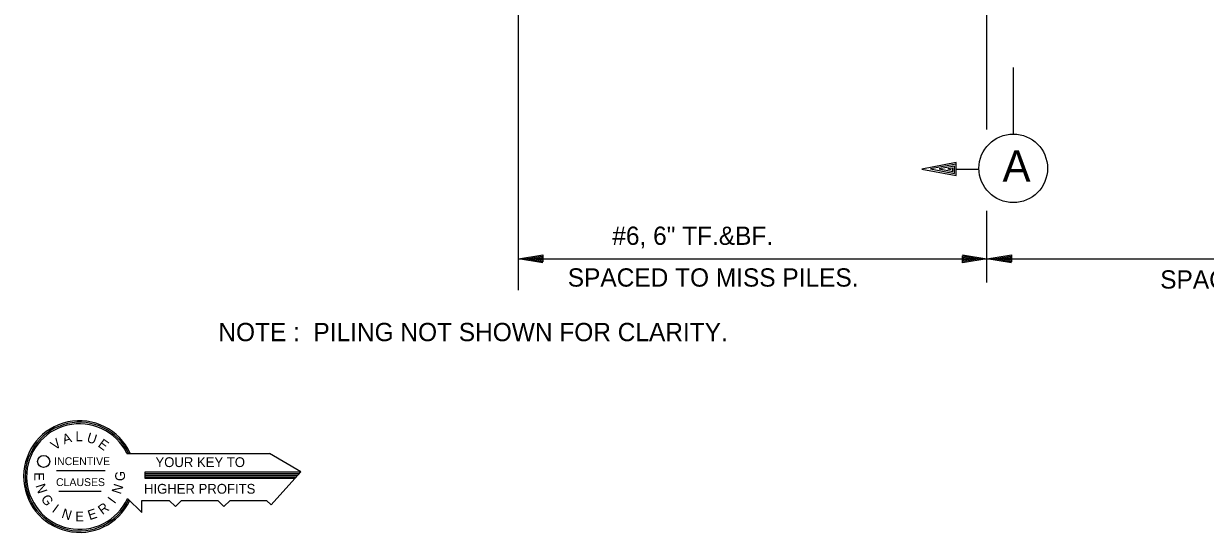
# Model space of a CAD drawing. Extents: x 6 to 106, y 3 to 74.
# Drawn here: x 6.02 to 30.14, y 3.5 to 13.89 of the extents above; entities that cross this region are included whole.
import ezdxf

# ---------------------------------------------------------------- set-up
doc = ezdxf.new("R2010")
doc.units = 0
for name, color, linetype in [('Level 1', 7, 'Continuous'), ('Level 2', 7, 'Continuous'), ('Level 22', 7, 'Continuous'), ('Level 25', 7, 'Continuous'), ('Level 3', 7, 'Continuous'), ('Level 50', 7, 'Continuous')]:
    doc.layers.add(name, color=color, linetype=linetype)

msp = doc.modelspace()

# ---------------------------------------------------------------- linework, layer by layer
at = {"layer": 'Level 1'}
for p, q in [((8.123, 5.113), (11.037, 5.113)), ((11.673, 4.737), (11.037, 5.113)), ((6.683, 4.763), (7.681, 4.763)), ((11.665, 4.727), (8.493, 4.727)), ((8.493, 4.727), (8.493, 4.603)), ((11.633, 4.693), (8.493, 4.693)), ((11.605, 4.661), (8.493, 4.661)), ((11.575, 4.627), (8.493, 4.627)), ((8.493, 4.603), (11.553, 4.603)), ((11.673, 4.737), (11.067, 4.059)), ((6.735, 4.341), (7.599, 4.341)), ((8.137, 4.193), (8.427, 3.903)), ((8.427, 3.903), (8.427, 4.153)), ((8.427, 4.153), (8.989, 4.153)), ((8.989, 4.153), (9.113, 4.029)), ((9.113, 4.029), (9.237, 4.153)), ((9.237, 4.153), (9.981, 4.153)), ((9.981, 4.153), (10.105, 4.029)), ((10.105, 4.029), (10.229, 4.153)), ((10.229, 4.153), (10.973, 4.153)), ((10.973, 4.153), (11.067, 4.059))]:
    msp.add_line(p, q, dxfattribs=at)
msp.add_circle((6.424, 4.948), 0.123, dxfattribs=at)
for radius, start, end in [(1.14, 24.569, 334.4243), (1.109, 25.3095, 334.4522), (1.078, 26.0896, 335.5943)]:
    msp.add_arc((7.155, 4.639), radius, start, end, dxfattribs=at)
at = {"layer": 'Level 25'}
for p, q in [((16.119, 8.444), (16.119, 14.856)), ((25.685, 11.73), (25.685, 14.558)), ((25.685, 8.6), (25.685, 10.065)), ((16.119, 9.085), (25.685, 9.085)), ((25.685, 9.085), (40.241, 9.085))]:
    msp.add_line(p, q, dxfattribs=at)
at = {"layer": 'Level 3'}
for p, q in [((26.22, 12.996), (26.22, 11.619)), ((25.054, 10.92), (25.52, 10.92))]:
    msp.add_line(p, q, dxfattribs=at)
msp.add_lwpolyline([(25.054, 11.018), (25.054, 11.053), (24.354, 10.92), (25.054, 10.789), (25.054, 11.018), (24.532, 10.922), (25.02, 10.829), (25.02, 10.98), (24.708, 10.922), (24.987, 10.87), (24.987, 10.94), (24.887, 10.922), (24.953, 10.91)], dxfattribs=at)
msp.add_circle((26.221, 10.934), 0.7, dxfattribs=at)
at = {"layer": 'Level 50'}
for p, q in [((16.119, 9.085), (16.119, 9.085)), ((16.258, 9.085), (16.258, 9.085)), ((25.547, 9.085), (25.547, 9.085)), ((25.685, 9.085), (25.685, 9.085)), ((25.685, 9.085), (25.685, 9.085)), ((25.824, 9.085), (25.824, 9.085))]:
    msp.add_line(p, q, dxfattribs=at)
for points in [[(16.618, 9.002), (16.119, 9.085), (16.618, 9.168), (16.618, 9.026), (16.258, 9.085), (16.597, 9.141), (16.597, 9.05), (16.391, 9.085), (16.575, 9.114), (16.575, 9.077), (16.53, 9.085)], [(25.187, 9.168), (25.685, 9.085), (25.187, 9.002), (25.187, 9.144), (25.547, 9.085), (25.208, 9.029), (25.208, 9.12), (25.413, 9.085), (25.229, 9.056), (25.229, 9.093), (25.275, 9.085)], [(26.184, 9.002), (25.685, 9.085), (26.184, 9.168), (26.184, 9.026), (25.824, 9.085), (26.163, 9.141), (26.163, 9.05), (25.957, 9.085), (26.141, 9.114), (26.141, 9.077), (26.096, 9.085)]]:
    msp.add_lwpolyline(points, dxfattribs=at)

# ---------------------------------------------------------------- texts
at = {"layer": 'Level 1'}
for s, height, p in [('L', 0.2, (7.073, 5.361)), ('INCENTIVE', 0.16, (6.639, 4.873)), ('YOUR KEY TO', 0.2, (8.707, 4.833)), ('CLAUSES', 0.16, (6.677, 4.445)), ('HIGHER PROFITS', 0.2, (8.473, 4.289)), ('E', 0.2, (7.069, 3.725))]:
    msp.add_text(s, height=height, dxfattribs=at).set_placement(p)
for s, rotation, p in [('V', 35.9204, (6.657, 5.167)), ('A', 18.0731, (6.843, 5.295)), ('U', 342.1107, (7.289, 5.353)), ('E', 323.9298, (7.517, 5.263)), ('E', 270, (6.233, 4.727)), ('G', 90, (8.085, 4.547)), ('N', 288.0821, (6.255, 4.455)), ('N', 71.9179, (7.997, 4.265)), ('G', 306.0537, (6.357, 4.183)), ('I', 53.5836, (7.873, 4.069)), ('I', 323.5836, (6.579, 3.929)), ('N', 341.9179, (6.775, 3.803)), ('E', 18.2241, (7.363, 3.747)), ('R', 36.2206, (7.625, 3.849))]:
    msp.add_text(s, height=0.2, rotation=rotation, dxfattribs=at).set_placement(p)
at = {"layer": 'Level 2'}
msp.add_text('A', height=0.64, dxfattribs=at).set_placement((26.003, 10.664))
at = {"layer": 'Level 22'}
for s, p in [('#6, 6" TF.&BF.', (18.035, 9.371)), ('SPACED TO MISS PILES.', (17.125, 8.518)), ('SPACED TO MISS PILES.', (29.222, 8.478)), ('NOTE :  PILING NOT SHOWN FOR CLARITY.', (9.991, 7.404))]:
    msp.add_text(s, height=0.37333, dxfattribs=at).set_placement(p)

doc.saveas('drawing.dxf')
